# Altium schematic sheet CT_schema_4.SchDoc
size 297 x 173 mm
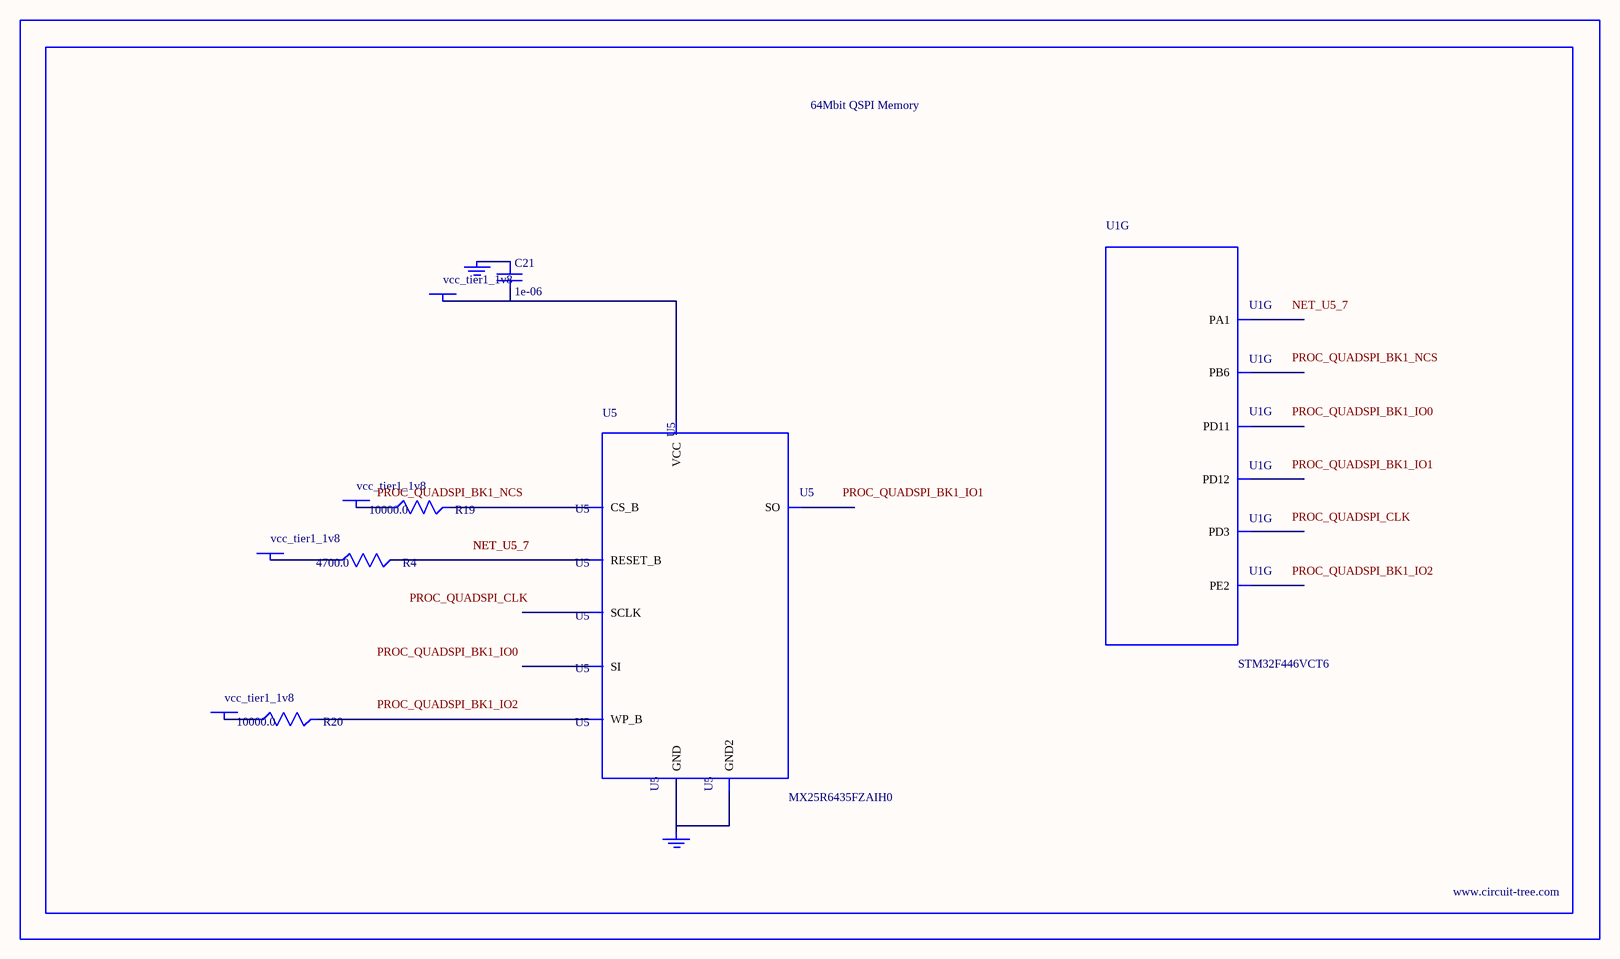
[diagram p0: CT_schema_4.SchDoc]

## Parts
BORDER3  (no value)
C21  1e-06  [C0603]
GND_INSTANCE_3_0  (no value)
GND_INSTANCE_3_1  (no value)
POWER_INSTANCE_3_0  vcc_tier1_1v8
POWER_INSTANCE_3_1  vcc_tier1_1v8
POWER_INSTANCE_3_2  vcc_tier1_1v8
POWER_INSTANCE_3_3  vcc_tier1_1v8
R4  4700.0  [R0603]
R19  10000.0  [R0603]
R20  10000.0  [R0603]
U1  STM32F446VCT6  [LQFP100]  (part G of 9)
U5  MX25R6435FZAIH0  [WSON-8-PAD]

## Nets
NetC21_1: C21.1 GND_INSTANCE_3_0.0(GND)
NetC21_2: C21.2 POWER_INSTANCE_3_2.0(PWR) U5.8(VCC)
NetGND_INSTANCE_3_1_0: GND_INSTANCE_3_1.0(GND) U5.4(GND) U5.PAD(GND2)
NetPOWER_INSTANCE_3_0_0: POWER_INSTANCE_3_0.0(PWR) R19.1
NetPOWER_INSTANCE_3_1_0: POWER_INSTANCE_3_1.0(PWR) R20.1
NetPOWER_INSTANCE_3_3_0: POWER_INSTANCE_3_3.0(PWR) R4.1
NetR4_2: R4.2 U5.7(RESET_B)
NetR19_2: R19.2 U5.1(CS_B)
NetR20_2: R20.2 U5.3(WP_B)

Not connected (* = marked no-connect by the designer): U1 1(PE2) 24(PA1) 58(PD11) 59(PD12) 84(PD3) 92(PB6); U5 2(SO) 5(SI) 6(SCLK)

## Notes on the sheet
- Labels drawn without touching a wire or pin: NET_U5_7, PROC_QUADSPI_BK1_IO0, PROC_QUADSPI_BK1_IO1, PROC_QUADSPI_BK1_IO2, PROC_QUADSPI_BK1_NCS, PROC_QUADSPI_CLK

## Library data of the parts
BORDER3 = BORDER_PAGE3
C21 = C0603C105K3RACTU
GND_INSTANCE_3_0 GND_INSTANCE_3_1 = GND
POWER_INSTANCE_3_0-POWER_INSTANCE_3_3 = PWR
R4 = RC0603JR-074K7L
R19 R20 = RC0603JR-0710KL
